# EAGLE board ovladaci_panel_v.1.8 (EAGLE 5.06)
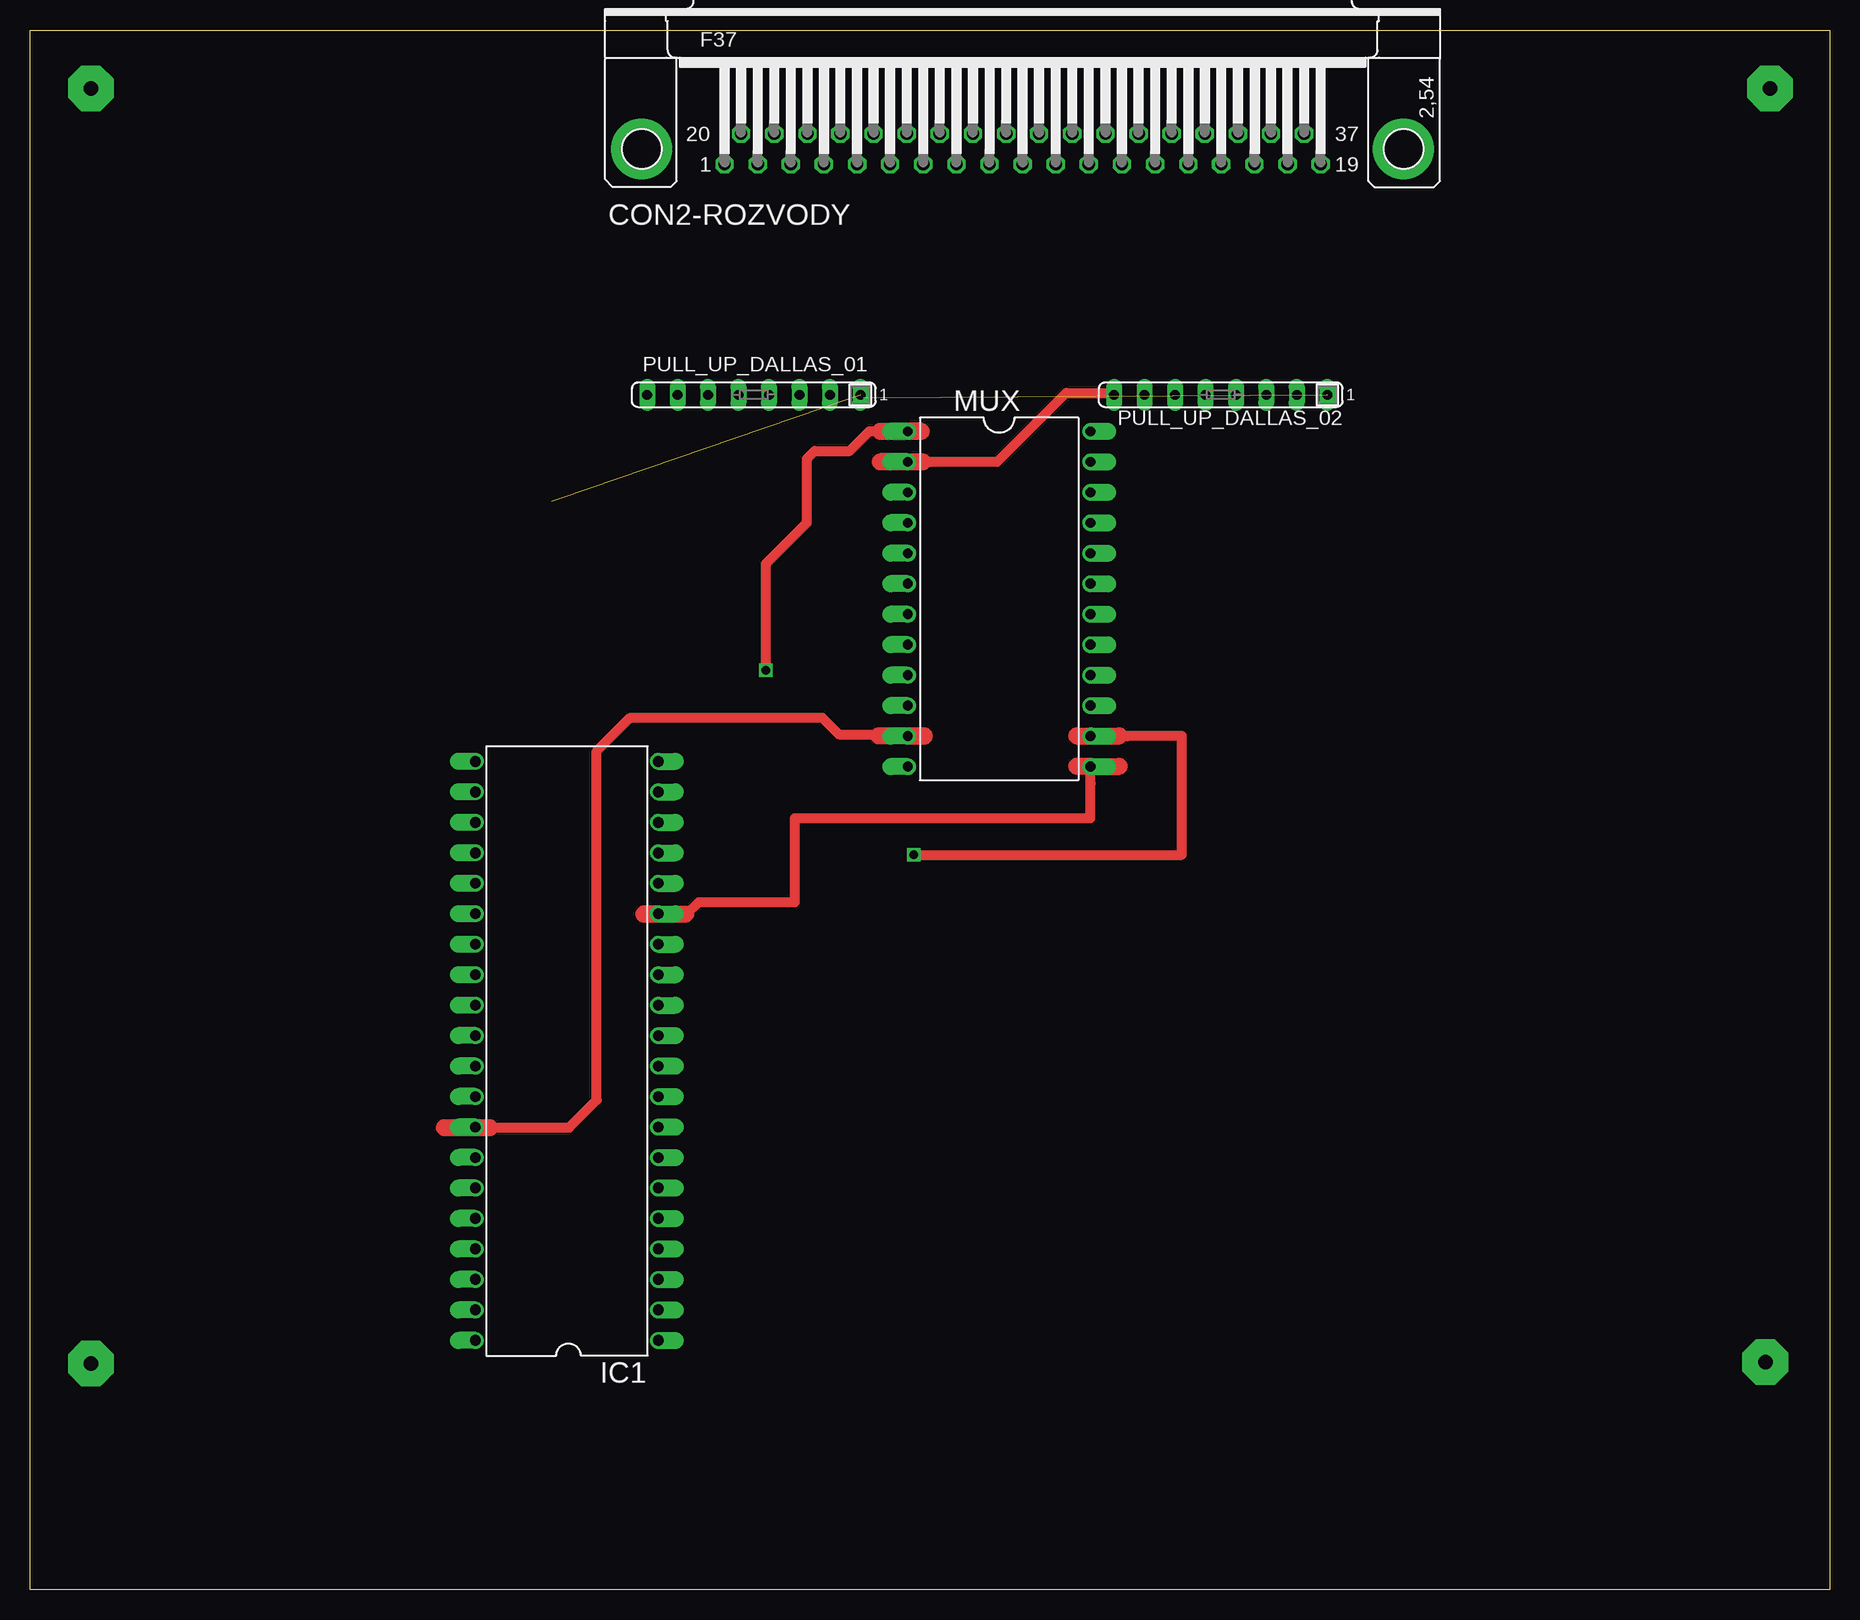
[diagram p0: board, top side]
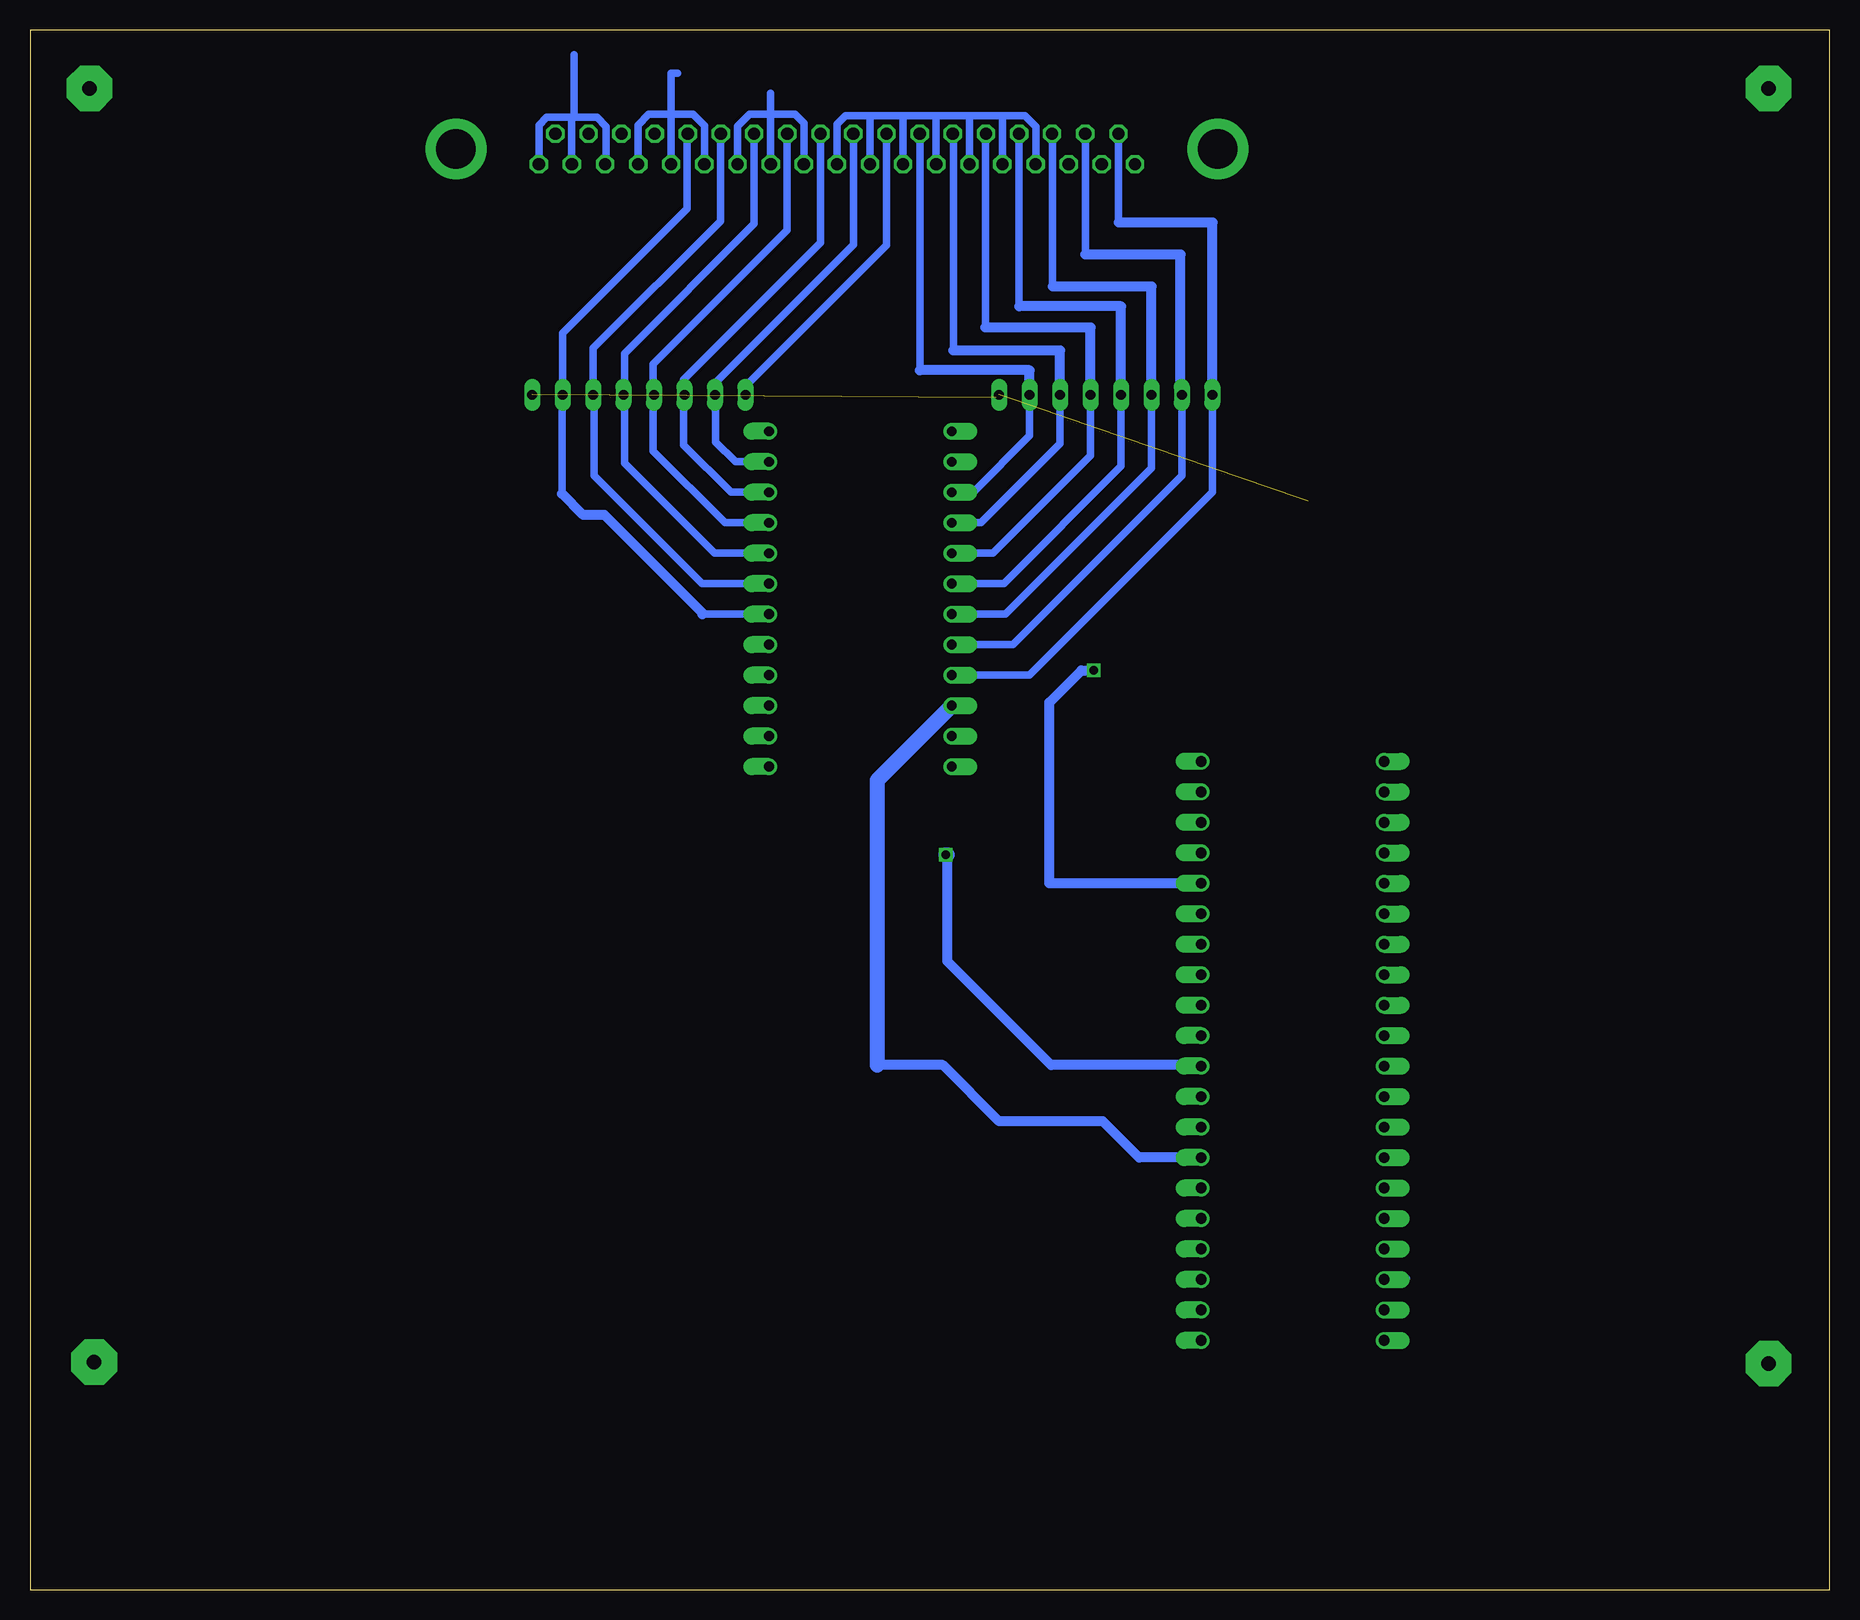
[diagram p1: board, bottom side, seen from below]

Size 150 x 130 mm. Coordinates in mm from the lower left corner, seen from the top.
Outline: 0,0 0,130 150,130 150,0 0,0
Copper layers (1*16): Top 0.035mm / dielectric 1.5mm / Bottom 0.035mm
Design rules "default *": minimum track width 0.2mm, minimum drill 24mil, track to track 8mil, track to pad 8mil, pad to pad 8mil, via to via 8mil, smd to smd 8mil, copper to edge 40mil, drill to drill 8mil, minimum pad ring 10mil, minimum via ring 8mil, stop-mask expansion 4mil, vias tented up to drill 0mil, thermal gap 10mil

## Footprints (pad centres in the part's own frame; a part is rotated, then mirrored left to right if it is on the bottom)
F37HP = drill 1.016 octagon: 1 -24.841,-1.27; 2 -22.073,-1.27; 3 -19.329,-1.27; 4 -16.561,-1.27; 5 -13.792,-1.27; 6 -11.049,-1.27; 7 -8.28,-1.27; 8 -5.512,-1.27; 9 -2.769,-1.27; 10 0,-1.27; 11 2.769,-1.27; 12 5.512,-1.27; 13 8.28,-1.27; 14 11.049,-1.27; 15 13.818,-1.27; 16 16.561,-1.27; 17 19.329,-1.27; 18 22.098,-1.27; 19 24.841,-1.27; 20 -23.47,1.27; 21 -20.701,1.27; 22 -17.932,1.27; 23 -15.189,1.27; 24 -12.421,1.27; 25 -9.652,1.27; 26 -6.909,1.27; 27 -4.14,1.27; 28 -1.372,1.27; 29 1.372,1.27; 30 4.14,1.27; 31 6.909,1.27; 32 9.677,1.27; 33 12.421,1.27; 34 15.189,1.27; 35 17.958,1.27; 36 20.701,1.27; 37 23.47,1.27 | drill 3.302 pad 5.08 round: G1 -31.75,0; G2 31.75,0
DIL40 = drill 0.9 offset: 1 -24.13,-7.62; 2 -21.59,-7.62; 3 -19.05,-7.62; 4 -16.51,-7.62; 5 -13.97,-7.62; 6 -11.43,-7.62; 7 -8.89,-7.62; 8 -6.35,-7.62; 9 -3.81,-7.62; 10 -1.27,-7.62; 11 1.27,-7.62; 12 3.81,-7.62; 13 6.35,-7.62; 14 8.89,-7.62; 15 11.43,-7.62; 16 13.97,-7.62; 17 16.51,-7.62; 18 19.05,-7.62; 19 21.59,-7.62; 20 24.13,-7.62; 21 24.13,7.62; 22 21.59,7.62; 23 19.05,7.62; 24 16.51,7.62; 25 13.97,7.62; 26 11.43,7.62; 27 8.89,7.62; 28 6.35,7.62; 29 3.81,7.62; 30 1.27,7.62; 31 -1.27,7.62; 32 -3.81,7.62; 33 -6.35,7.62; 34 -8.89,7.62; 35 -11.43,7.62; 36 -13.97,7.62; 37 -16.51,7.62; 38 -19.05,7.62; 39 -21.59,7.62; 40 -24.13,7.62
DIL24-6 = drill 0.813 pad 1.422 offset: 1 -13.97,-7.62; 2 -11.43,-7.62; 3 -8.89,-7.62; 4 -6.35,-7.62; 5 -3.81,-7.62; 6 -1.27,-7.62; 7 1.27,-7.62; 8 3.81,-7.62; 9 6.35,-7.62; 10 8.89,-7.62; 11 11.43,-7.62; 12 13.97,-7.62; 13 13.97,7.62; 14 11.43,7.62; 15 8.89,7.62; 16 6.35,7.62; 17 3.81,7.62; 18 1.27,7.62; 19 -1.27,7.62; 20 -3.81,7.62; 21 -6.35,7.62; 22 -8.89,7.62; 23 -11.43,7.62; 24 -13.97,7.62
SIL8 = drill 0.813 long: 1 -8.89,0; 2 -6.35,0; 3 -3.81,0; 4 -1.27,0; 5 1.27,0; 6 3.81,0; 7 6.35,0; 8 8.89,0

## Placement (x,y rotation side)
CON2-ROZVODY  DALLAS_ROZVODY  [F37HP]  82.74,120.08 0 top
IC1  PIC18F4550  [DIL40]  44.75,44.9 90 top
MUX  HCF4067B  [DIL24-6]  80.78,82.57 270 top
PULL_UP_DALLAS_01  4k7  [SIL8]  60.33,99.59 180 top
PULL_UP_DALLAS_02  4k7  [SIL8]  99.25,99.59 180 top

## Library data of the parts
CON2-ROZVODY = con-subd
IC1 MUX = ic-package
PULL_UP_DALLAS_01 PULL_UP_DALLAS_02 = resistor-sil

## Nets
CERPADLO: CON2-ROZVODY.1
DS-01: CON2-ROZVODY.20 MUX.9 PULL_UP_DALLAS_01.8
DS-02: CON2-ROZVODY.21 MUX.8 PULL_UP_DALLAS_01.7
DS-03: CON2-ROZVODY.22 MUX.7 PULL_UP_DALLAS_01.6
DS-04: CON2-ROZVODY.23 MUX.6 PULL_UP_DALLAS_01.5
DS-05: CON2-ROZVODY.24 MUX.5 PULL_UP_DALLAS_01.4
DS-06: CON2-ROZVODY.25 MUX.4 PULL_UP_DALLAS_01.3
DS-07: CON2-ROZVODY.26 MUX.3 PULL_UP_DALLAS_01.2
DS-08: CON2-ROZVODY.27 MUX.2 PULL_UP_DALLAS_02.8
DS-09: CON2-ROZVODY.28 MUX.23 PULL_UP_DALLAS_02.7
DS-10: CON2-ROZVODY.29 MUX.22 PULL_UP_DALLAS_02.6
DS-11: CON2-ROZVODY.30 MUX.21 PULL_UP_DALLAS_02.5
DS-12: CON2-ROZVODY.31 MUX.20 PULL_UP_DALLAS_02.4
DS-13: CON2-ROZVODY.32 MUX.19 PULL_UP_DALLAS_02.3
DS-14: CON2-ROZVODY.33 MUX.18 PULL_UP_DALLAS_02.2
FUSE-02: CON2-ROZVODY.14 CON2-ROZVODY.15 CON2-ROZVODY.16
FUSE-03: CON2-ROZVODY.17 CON2-ROZVODY.18 CON2-ROZVODY.19
INHIBIT: MUX.15
KOTEL: CON2-ROZVODY.2
MCLR/VPP/RE3: IC1.1
N$10: CON2-ROZVODY.11 CON2-ROZVODY.12 CON2-ROZVODY.13
NOC: CON2-ROZVODY.3
OSC1/CLK: IC1.13
OSC2/CLKO/RA6: IC1.14
POM_IN: CON2-ROZVODY.35
POM_OUT: CON2-ROZVODY.36
RA0: IC1.2
RA1: IC1.3
RA2: IC1.4
RA3: IC1.5
RA4: IC1.6
RA5/AN4/SS/HLVDIN/C2OUT: IC1.7 MUX.10
RB0/AN12/INT0/FLT0/SDI/SDA: IC1.33 MUX.11
RB1: IC1.34
RB2: IC1.35
RB3: IC1.36
RB4: IC1.37
RB5/PGM: IC1.38
RB6/PGC: IC1.39
RB7/PGD: IC1.40
RC0/T1OSO/T13CK: IC1.15 MUX.13
RC1/T1OSI/CCP2(1)/UOE: IC1.16 MUX.1
RC2/CCP1: IC1.17
RC4/D-/VM: IC1.23
RC5/D+/VP: IC1.24
RC6/TX/CK: IC1.25
RC7/RX/DT/SDO: IC1.26
RD0: IC1.19
RD1: IC1.20
RD2: IC1.21
RD3: IC1.22
RD4/SPP4: IC1.27
RD5/SPP5/P1B: IC1.28
RD6/SPP6/P1C: IC1.29
RD7/SPP7/P1D: IC1.30
RE0/AN5/CK1SPP: IC1.8
RE1/AN6/CK2SPP: IC1.9
RE2/AN7/OESPP: IC1.10 MUX.14
VDD: PULL_UP_DALLAS_01.1 PULL_UP_DALLAS_02.1
VSS: CON2-ROZVODY.4 CON2-ROZVODY.5 CON2-ROZVODY.6 CON2-ROZVODY.7 CON2-ROZVODY.8 CON2-ROZVODY.9 CON2-ROZVODY.10
VUSB: IC1.18

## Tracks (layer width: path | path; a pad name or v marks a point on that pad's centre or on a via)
DS-01
  Bottom 0.61: MUX.9 73.15,76.23 66.67,76.23 51.44,91.47 PULL_UP_DALLAS_01.8 | 59.27,113.95 CON2-ROZVODY.20
  Bottom 0.813: 59.27,113.95 51.43,113.95 PULL_UP_DALLAS_01.8
DS-02
  Bottom 0.61: PULL_UP_DALLAS_01.7 53.98,92.86 68.07,78.78 73.15,78.78 MUX.8 | 62.04,111.29 CON2-ROZVODY.21
  Bottom 0.813: 62.04,111.29 54.1,111.29 54.1,99.59 PULL_UP_DALLAS_01.7
DS-03
  Bottom 0.61: PULL_UP_DALLAS_01.6 56.52,93.5 68.7,81.31 73.15,81.31 MUX.7 | 64.77,108.62 64.77,121.35
  Bottom 0.813: PULL_UP_DALLAS_01.6 56.52,108.62 64.77,108.62 | 64.77,121.35 CON2-ROZVODY.22
DS-04
  Bottom 0.61: PULL_UP_DALLAS_01.5 59.06,93.63 68.83,83.86 73.15,83.86 MUX.6 | 67.56,106.97 67.56,121.35
  Bottom 0.813: PULL_UP_DALLAS_01.5 59.06,106.97 67.56,106.97 | 67.56,121.35 CON2-ROZVODY.23
DS-05
  Bottom 0.61: PULL_UP_DALLAS_01.4 61.6,94.52 69.72,86.39 73.15,86.39 MUX.5 | 70.36,105.19 70.36,121.35
  Bottom 0.813: PULL_UP_DALLAS_01.4 61.6,105.19 70.36,105.19 | 70.36,121.35 CON2-ROZVODY.24
DS-06
  Bottom 0.61: PULL_UP_DALLAS_01.3 64.14,95.53 70.74,88.94 73.15,88.94 MUX.4 | 73.02,103.29 73.02,121.35
  Bottom 0.813: PULL_UP_DALLAS_01.3 64.14,103.29 73.02,103.29 | 73.02,121.35 CON2-ROZVODY.25
DS-07
  Bottom 0.61: PULL_UP_DALLAS_01.2 66.68,96.17 71.37,91.47 73.15,91.47 MUX.3 | 75.82,101.64 75.82,121.35
  Bottom 0.813: PULL_UP_DALLAS_01.2 66.68,101.64 75.82,101.64 | 75.82,121.35 CON2-ROZVODY.26
DS-08
  Top 0.813: 80.77,94.14 80.63,94 | 80.77,94.14 86.36,99.73 90.22,99.73 PULL_UP_DALLAS_02.8 | 74.42,94.02 80.64,94.02 80.77,94.14 | 70.88,94 72.89,94 72.9,94.02
  Top 1.422: 70.88,94 MUX.2 | 70.86,94.02 72.9,94.02 74.42,94.02
  Bottom 0.61: CON2-ROZVODY.27 78.6,112.06 90.3,100.36 90.3,99.66 PULL_UP_DALLAS_02.8
DS-09
  Bottom 0.61: MUX.23 91.17,94 92.83,95.67 92.83,99.52 PULL_UP_DALLAS_02.7 92.83,99.66 92.83,100.62 81.37,112.09 CON2-ROZVODY.28
DS-10
  Bottom 0.61: MUX.22 91.55,91.46 95.5,95.41 95.5,99.53 PULL_UP_DALLAS_02.6 95.5,99.65 95.5,100.87 84.11,112.26 CON2-ROZVODY.29
DS-11
  Bottom 0.61: MUX.21 92.06,88.92 98.04,94.9 98.04,99.53 PULL_UP_DALLAS_02.5 98.04,99.65 98.04,102.14 86.88,113.31 CON2-ROZVODY.30
DS-12
  Bottom 0.61: MUX.20 92.95,86.38 100.45,93.89 100.45,99.52 PULL_UP_DALLAS_02.4 100.45,99.66 100.45,103.03 89.65,113.84 CON2-ROZVODY.31
DS-13
  Bottom 0.61: MUX.19 93.97,83.84 103,92.87 103,99.52 PULL_UP_DALLAS_02.3 103.06,103.47 92.45,114.08 92.45,121.31 CON2-ROZVODY.32
DS-14
  Bottom 0.61: MUX.18 93.97,81.3 | 105.66,91.35 105.66,99.53 PULL_UP_DALLAS_02.2 105.6,104.74 95.25,115.1 95.25,121.26 CON2-ROZVODY.33
  Bottom 0.813: 93.97,81.3 93.97,81.43 102.11,89.57 103.88,89.57 105.66,91.35
FUSE-02
  Bottom 0.61: CON2-ROZVODY.14 93.79,122.02 94.74,122.97 96.52,122.97 | 96.52,122.97 98.42,122.97 99.31,122.08 99.31,118.82 CON2-ROZVODY.16 | 96.56,122.46 96.56,122.93 96.52,122.97 | 96.56,122.46 CON2-ROZVODY.15 | 96.01,126.4 96.56,126.4 96.56,122.46
FUSE-03
  Bottom 0.61: CON2-ROZVODY.19 107.58,122.07 106.93,122.72 104.65,122.72 | 104.65,122.72 102.74,122.72 101.98,121.95 101.98,118.9 CON2-ROZVODY.17 | CON2-ROZVODY.18 104.84,122.53 104.65,122.72 | 104.65,122.72 104.65,127.92
N$3  (via drill 1.2 pad 3.81)
  other vias: 5.08,125.13
N$4  (via drill 1.2 pad 3.81)
  other vias: 145.03,125.13
N$8  (via drill 1.2 pad 3.81)
  other vias: 5.08,18.83
N$9  (via drill 1.2 pad 3.81)
  other vias: 144.65,18.96
N$10
  Bottom 0.61: CON2-ROZVODY.13 91.02,121.99 90.04,122.97 88.26,122.97 | 88.26,122.97 86.23,122.97 85.47,122.21 85.47,118.85 CON2-ROZVODY.11 | CON2-ROZVODY.12 88.25,122.96 88.26,122.97 | 88.26,122.97 88.26,124.75
RA5/AN4/SS/HLVDIN/C2OUT
  Bottom 0.813: IC1.7 57.56,36.01 60.58,39.02 69.21,39.02 73.91,43.72 79.37,43.72
  Bottom 1.27: 79.37,43.72 79.37,67.47 MUX.10
RB0/AN12/INT0/FLT0/SDI/SDA
  Top 0.813: IC1.33 37.16,38.52 38.35,38.52 44.96,38.52 47.24,40.8 47.24,69.89 50.04,72.68 66.04,72.68 67.44,71.28 73.02,71.28 MUX.11
  Top 1.422: 34.54,38.52 38.35,38.52 | MUX.11 74.54,71.14 74.55,71.16 70.74,71.16
RB5/PGM
  Bottom 0.61: IC1.38 37.04,25.94 35.27,25.94
RB6/PGC
  Bottom 0.61: IC1.39 37.04,23.4 36.07,23.4 36.07,23.35
RB7/PGD
  Bottom 0.61: IC1.40 37.1,20.74
RC0/T1OSO/T13CK
  Top 0.813: MUX.13 88.4,67.22 88.39,67.22 88.39,64.3 63.75,64.3 63.75,57.31 55.75,57.31 54.73,56.3
  Top 1.27: 54.61,56.3 54.73,56.3
  Top 1.422: 88.4,68.61 90.8,68.61 | MUX.13 88.4,68.61 | 88.4,68.61 87.25,68.61 | IC1.15 51.21,56.33 51.18,56.3 54.61,56.3
RC1/T1OSI/CCP2(1)/UOE  (via drill 0.7)
  Top 0.813: v61.34,76.62 61.34,85.51 64.77,88.94 64.77,94.27 65.4,94.9 68.32,94.9 69.97,96.56 70.86,96.56
  Top 1.422: MUX.1 74.28,96.54 74.29,96.56 70.86,96.56
  Bottom 0.813: IC1.16 65.02,58.87 65.02,73.95 62.35,76.62 v61.34,76.62
RE2/AN7/OESPP  (via drill 0.7)
  Top 0.813: v73.66,61.25 96.01,61.25 96.01,71.16 92.07,71.16 | 92.07,71.16 91.45,71.16 91.45,71.14 | 92.07,71.16 87.25,71.16
  Top 1.422: 88.4,71.16 MUX.14 | 88.4,71.16 90.8,71.16 | 87.25,71.16 88.4,71.16
  Bottom 0.813: v73.66,61.25 73.53,61.12 73.53,52.36 64.89,43.72 52.37,43.72
  Bottom 1.27: v73.66,61.25 73.53,61.25 | IC1.10 52.37,43.72
VDD  (3 unrouted)
  Bottom 0.813: PULL_UP_DALLAS_01.1 69.46,99.35
VSS
  Bottom 0.61: CON2-ROZVODY.10 82.74,122.14 82.04,122.84 80.01,122.84 | 68.96,122.84 67.05,122.84 66.17,121.95 66.17,118.83 CON2-ROZVODY.4 | 68.96,122.84 71.75,122.84 | 71.75,122.84 74.29,122.84 | 74.29,122.84 77.34,122.84 | 77.34,122.84 80.01,122.84 | CON2-ROZVODY.5 68.95,122.83 68.96,122.84 | CON2-ROZVODY.6 71.69,122.78 71.75,122.84 | CON2-ROZVODY.7 74.46,122.68 74.29,122.84 | CON2-ROZVODY.9 79.97,122.81 80.01,122.84 | CON2-ROZVODY.8 77.23,122.73 77.34,122.84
